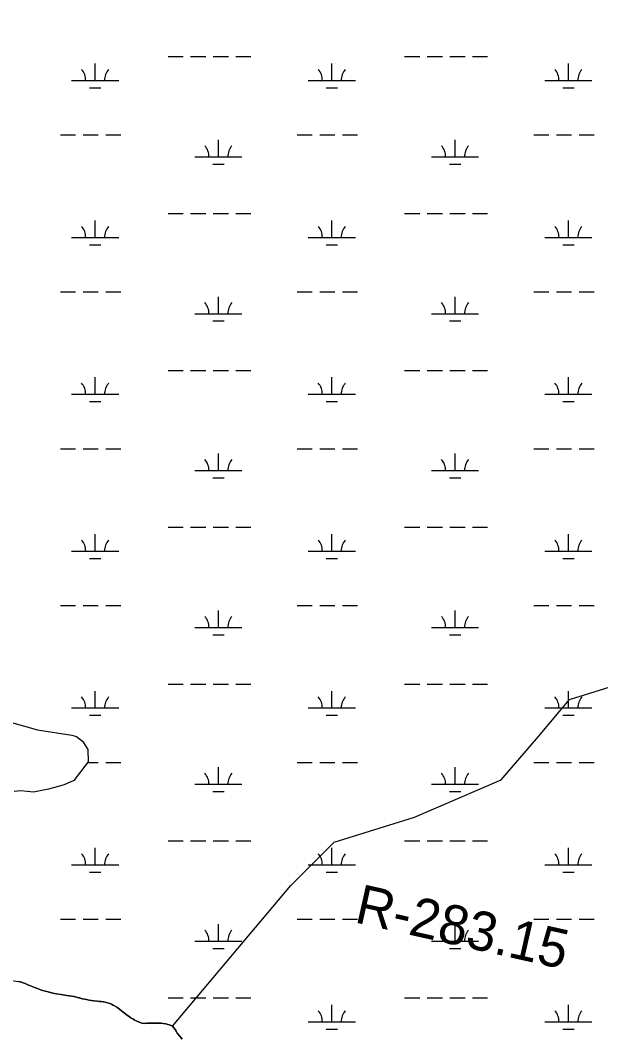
# Model space of a CAD drawing. Extents: x 3192927 to 3230760, y 831141 to 856475.
# Drawn here: x 3214470 to 3215700, y 838041 to 840200 of the extents above; entities that cross this region are included whole.
import ezdxf

# ---------------------------------------------------------------- set-up
doc = ezdxf.new("R2010")
doc.units = 0
for name, color, linetype in [('V-RIVR-RANG-IDEN', 7, 'Continuous'), ('V-SITE-VEGE', 7, 'Continuous'), ('V-TOPO-SHOR', 7, 'Continuous'), ('V-WETL-SWMP', 7, 'Continuous')]:
    doc.layers.add(name, color=color, linetype=linetype)

msp = doc.modelspace()

# ---------------------------------------------------------------- linework, layer by layer
at = {"layer": 'V-SITE-VEGE'}
for p, q in [((3214450.5, 838711.3), (3214505.8, 838695.7)), ((3214505.8, 838695.7), (3214578.9, 838684.3)), ((3214578.9, 838684.3), (3214588.3, 838681.6)), ((3214588.3, 838681.6), (3214601.1, 838671.3)), ((3214601.1, 838671.3), (3214612.8, 838654.1)), ((3214612.8, 838654.1), (3214613.1, 838627.8)), ((3214613.1, 838627.8), (3214583.3, 838588.2)), ((3214562.2, 838579.1), (3214529.4, 838569.5)), ((3214583.3, 838588.2), (3214562.2, 838579.1)), ((3214470.9, 838566.2), (3214456.3, 838564.5)), ((3214497.4, 838563.6), (3214470.9, 838566.2)), ((3214529.4, 838569.5), (3214497.4, 838563.6)), ((3214451.5, 838164.2), (3214469.8, 838160.9)), ((3214469.8, 838160.9), (3214475.6, 838159.1)), ((3214475.6, 838159.1), (3214479.8, 838157.5)), ((3214479.8, 838157.5), (3214484.2, 838155.6)), ((3214484.2, 838155.6), (3214491.2, 838153)), ((3214491.2, 838153), (3214501.8, 838148.5)), ((3214501.8, 838148.5), (3214506.2, 838146.7)), ((3214506.2, 838146.7), (3214512.3, 838144.4)), ((3214512.3, 838144.4), (3214517.3, 838142.6)), ((3214517.3, 838142.6), (3214522.5, 838141.1)), ((3214522.5, 838141.1), (3214525.5, 838140.5)), ((3214525.5, 838140.5), (3214538.3, 838137.4)), ((3214538.3, 838137.4), (3214541.9, 838136.6)), ((3214541.9, 838136.6), (3214546, 838136)), ((3214546, 838136), (3214556, 838134.1)), ((3214556, 838134.1), (3214564.2, 838132.9)), ((3214564.2, 838132.9), (3214583.5, 838129.7)), ((3214583.5, 838129.7), (3214590.7, 838128.1)), ((3214590.7, 838128.1), (3214601.1, 838125.4)), ((3214601.1, 838125.4), (3214609.8, 838123.6)), ((3214609.8, 838123.6), (3214615.8, 838122.3)), ((3214615.8, 838122.3), (3214625.2, 838120.9)), ((3214625.2, 838120.9), (3214633, 838120.4)), ((3214633, 838120.4), (3214637.7, 838119.8)), ((3214637.7, 838119.8), (3214641.1, 838119.6)), ((3214641.1, 838119.6), (3214649.7, 838118.3)), ((3214649.7, 838118.3), (3214659.3, 838115.1)), ((3214659.3, 838115.1), (3214662.9, 838113.6)), ((3214662.9, 838113.6), (3214666.1, 838112)), ((3214666.1, 838112), (3214669.3, 838110.2)), ((3214669.3, 838110.2), (3214673.9, 838107.5)), ((3214673.9, 838107.5), (3214677.3, 838105.3)), ((3214677.3, 838105.3), (3214680.1, 838102.9)), ((3214680.1, 838102.9), (3214684.1, 838099.8)), ((3214684.1, 838099.8), (3214687.3, 838096.8)), ((3214687.3, 838096.8), (3214696.5, 838089.7)), ((3214696.5, 838089.7), (3214700.1, 838087.5)), ((3214700.1, 838087.5), (3214704.7, 838084.3)), ((3214704.7, 838084.3), (3214707.9, 838082.6)), ((3214707.9, 838082.6), (3214711.1, 838080.6)), ((3214711.1, 838080.6), (3214718.3, 838076.8)), ((3214718.3, 838076.8), (3214725, 838074.5)), ((3214725, 838074.5), (3214728.2, 838073.7)), ((3214728.2, 838073.7), (3214732.4, 838073.1)), ((3214732.4, 838073.1), (3214737.6, 838073.2)), ((3214737.6, 838073.2), (3214741.6, 838073.4)), ((3214741.6, 838073.4), (3214747.3, 838073.4)), ((3214747.3, 838073.4), (3214751.9, 838073.7)), ((3214751.9, 838073.7), (3214763.9, 838073.7)), ((3214763.9, 838073.7), (3214768.1, 838073.3)), ((3214768.1, 838073.3), (3214772.4, 838072.8)), ((3214772.4, 838072.8), (3214778.2, 838072.2)), ((3214778.2, 838072.2), (3214782, 838071)), ((3214782, 838071), (3214785.8, 838070.1)), ((3214785.8, 838070.1), (3214792.4, 838066.9)), ((3214792.4, 838066.9), (3214795.4, 838063.3)), ((3214795.4, 838063.3), (3214797.6, 838060)), ((3214797.6, 838060), (3214799.8, 838056.2)), ((3214799.8, 838056.2), (3214802.4, 838052.6)), ((3214802.4, 838052.6), (3214807.4, 838046.3)), ((3214807.4, 838046.3), (3214809.9, 838042.9)), ((3214809.9, 838042.9), (3214812.9, 838039.5))]:
    msp.add_line(p, q, dxfattribs=at)
at = {"layer": 'V-TOPO-SHOR'}
for points in [[(3214792.4, 838066.9), (3215042.9, 838365.4), (3215134.9, 838457.5), (3215305.7, 838510.2), (3215489.6, 838589.2), (3215568.4, 838681.3), (3215634.1, 838760.2), (3215804.9, 838812.9), (3215883.7, 838891.9), (3216094, 838931.5), (3216225.3, 839023.6), (3216238.4, 839076.2), (3216251.5, 839168.2), (3216251.4, 839299.6), (3216251.2, 839483.6), (3216277.3, 839693.9), (3216303.5, 839878), (3216434.7, 840101.5), (3216526.6, 840272.5), (3216565.9, 840456.5), (3216552.6, 840627.4), (3216591.9, 840785.1), (3216631.2, 840903.4), (3216657.5, 840956)], [(3214450.5, 838711.3), (3214505.8, 838695.7), (3214578.9, 838684.3), (3214588.3, 838681.6), (3214601.1, 838671.3), (3214612.8, 838654.1), (3214613.1, 838627.8), (3214583.3, 838588.2), (3214562.2, 838579.1), (3214529.4, 838569.5), (3214497.4, 838563.6), (3214470.9, 838566.2), (3214456.3, 838564.5)], [(3214556, 838134.1), (3214550, 838135.2), (3214546, 838136), (3214541.9, 838136.6), (3214538.3, 838137.4), (3214533.7, 838138.5), (3214528.5, 838139.7), (3214525.5, 838140.5), (3214522.5, 838141.1), (3214517.3, 838142.6), (3214512.3, 838144.4), (3214506.2, 838146.7), (3214501.8, 838148.5), (3214491.2, 838153), (3214484.2, 838155.6), (3214479.8, 838157.5), (3214475.6, 838159.1), (3214469.8, 838160.9), (3214465.4, 838161.6)], [(3214812.9, 838039.5), (3214809.9, 838042.9), (3214807.4, 838046.3), (3214802.4, 838052.6), (3214799.8, 838056.2), (3214797.6, 838060), (3214795.4, 838063.3), (3214792.4, 838066.9), (3214785.8, 838070.1), (3214782, 838071), (3214778.2, 838072.2), (3214772.4, 838072.8), (3214768.1, 838073.3), (3214763.9, 838073.7), (3214758.9, 838073.7), (3214755.5, 838073.7), (3214751.9, 838073.7), (3214747.3, 838073.4), (3214741.6, 838073.4), (3214737.6, 838073.2), (3214732.4, 838073.1), (3214728.2, 838073.7), (3214725, 838074.5), (3214722, 838075.5), (3214718.3, 838076.8), (3214714.1, 838079), (3214711.1, 838080.6), (3214707.9, 838082.6), (3214704.7, 838084.3), (3214700.1, 838087.5), (3214696.5, 838089.7), (3214690.3, 838094.4), (3214687.3, 838096.8), (3214684.1, 838099.8), (3214680.1, 838102.9), (3214677.3, 838105.3), (3214673.9, 838107.5), (3214669.3, 838110.2), (3214666.1, 838112), (3214662.9, 838113.6), (3214659.3, 838115.1), (3214654.5, 838116.7), (3214649.7, 838118.3), (3214646.3, 838118.9), (3214641.1, 838119.6), (3214637.7, 838119.8), (3214633, 838120.4), (3214625.2, 838120.9), (3214615.8, 838122.3), (3214609.8, 838123.6), (3214601.1, 838125.4), (3214595.3, 838126.9), (3214590.7, 838128.1), (3214583.5, 838129.7), (3214577.9, 838130.6), (3214572.4, 838131.6), (3214564.2, 838132.9), (3214559.8, 838133.5), (3214556, 838134.1)]]:
    msp.add_lwpolyline(points, dxfattribs=at)
at = {"layer": 'V-WETL-SWMP'}
for p, q in [((3214782.7, 840123.4), (3214814.7, 840123.4)), ((3214830.7, 840123.4), (3214862.7, 840123.4)), ((3214878.7, 840123.4), (3214910.7, 840123.4)), ((3214926.7, 840123.4), (3214958.7, 840123.4)), ((3215284.6, 840123.4), (3215316.6, 840123.4)), ((3215332.6, 840123.4), (3215364.6, 840123.4)), ((3215380.6, 840123.4), (3215412.6, 840123.4)), ((3215428.6, 840123.4), (3215460.6, 840123.4)), ((3214628.1, 840072.6), (3214628.1, 840108.6)), ((3215130, 840072.6), (3215130, 840108.6)), ((3215631.9, 840072.6), (3215631.9, 840108.6)), ((3214578.1, 840072.6), (3214678.1, 840072.6)), ((3215080, 840072.6), (3215180, 840072.6)), ((3215581.9, 840072.6), (3215681.9, 840072.6)), ((3214616.1, 840057.2), (3214640.1, 840057.2)), ((3215118, 840057.2), (3215142, 840057.2)), ((3215619.9, 840057.2), (3215643.9, 840057.2)), ((3214554.7, 839957.2), (3214586.7, 839957.2)), ((3214602.7, 839957.2), (3214634.7, 839957.2)), ((3214650.7, 839957.2), (3214682.7, 839957.2)), ((3214889.6, 839910.8), (3214889.6, 839946.8)), ((3215056.6, 839957.2), (3215088.6, 839957.2)), ((3215104.6, 839957.2), (3215136.6, 839957.2)), ((3215152.6, 839957.2), (3215184.6, 839957.2)), ((3215391.5, 839910.8), (3215391.5, 839946.8)), ((3215558.5, 839957.2), (3215590.5, 839957.2)), ((3215606.5, 839957.2), (3215638.5, 839957.2)), ((3215654.5, 839957.2), (3215686.5, 839957.2)), ((3214839.6, 839910.8), (3214939.6, 839910.8)), ((3214877.6, 839895.3), (3214901.6, 839895.3)), ((3215341.5, 839910.8), (3215441.5, 839910.8)), ((3215379.5, 839895.3), (3215403.5, 839895.3)), ((3214782.7, 839790.7), (3214814.7, 839790.7)), ((3214830.7, 839790.7), (3214862.7, 839790.7)), ((3214878.7, 839790.7), (3214910.7, 839790.7)), ((3214926.7, 839790.7), (3214958.7, 839790.7)), ((3215284.6, 839790.7), (3215316.6, 839790.7)), ((3215332.6, 839790.7), (3215364.6, 839790.7)), ((3215380.6, 839790.7), (3215412.6, 839790.7)), ((3215428.6, 839790.7), (3215460.6, 839790.7)), ((3214628.1, 839740), (3214628.1, 839776)), ((3215130, 839740), (3215130, 839776)), ((3215631.9, 839740), (3215631.9, 839776)), ((3214578.1, 839740), (3214678.1, 839740)), ((3214616.1, 839724.5), (3214640.1, 839724.5)), ((3215080, 839740), (3215180, 839740)), ((3215118, 839724.5), (3215142, 839724.5)), ((3215581.9, 839740), (3215681.9, 839740)), ((3215619.9, 839724.5), (3215643.9, 839724.5)), ((3214554.7, 839624.5), (3214586.7, 839624.5)), ((3214602.7, 839624.5), (3214634.7, 839624.5)), ((3214650.7, 839624.5), (3214682.7, 839624.5)), ((3215056.6, 839624.5), (3215088.6, 839624.5)), ((3215104.6, 839624.5), (3215136.6, 839624.5)), ((3215152.6, 839624.5), (3215184.6, 839624.5)), ((3215558.5, 839624.5), (3215590.5, 839624.5)), ((3215606.5, 839624.5), (3215638.5, 839624.5)), ((3215654.5, 839624.5), (3215686.5, 839624.5)), ((3214889.6, 839578.1), (3214889.6, 839614.1)), ((3215391.5, 839578.1), (3215391.5, 839614.1)), ((3214839.6, 839578.1), (3214939.6, 839578.1)), ((3215341.5, 839578.1), (3215441.5, 839578.1)), ((3214877.6, 839562.7), (3214901.6, 839562.7)), ((3215379.5, 839562.7), (3215403.5, 839562.7)), ((3214628.1, 839407.3), (3214628.1, 839443.3)), ((3214782.7, 839458), (3214814.7, 839458)), ((3214830.7, 839458), (3214862.7, 839458)), ((3214878.7, 839458), (3214910.7, 839458)), ((3214926.7, 839458), (3214958.7, 839458)), ((3215130, 839407.3), (3215130, 839443.3)), ((3215284.6, 839458), (3215316.6, 839458)), ((3215332.6, 839458), (3215364.6, 839458)), ((3215380.6, 839458), (3215412.6, 839458)), ((3215428.6, 839458), (3215460.6, 839458)), ((3215631.9, 839407.3), (3215631.9, 839443.3)), ((3214578.1, 839407.3), (3214678.1, 839407.3)), ((3215080, 839407.3), (3215180, 839407.3)), ((3215581.9, 839407.3), (3215681.9, 839407.3)), ((3214616.1, 839391.8), (3214640.1, 839391.8)), ((3215118, 839391.8), (3215142, 839391.8)), ((3215619.9, 839391.8), (3215643.9, 839391.8)), ((3214554.7, 839291.8), (3214586.7, 839291.8)), ((3214602.7, 839291.8), (3214634.7, 839291.8)), ((3214650.7, 839291.8), (3214682.7, 839291.8)), ((3215056.6, 839291.8), (3215088.6, 839291.8)), ((3215104.6, 839291.8), (3215136.6, 839291.8)), ((3215152.6, 839291.8), (3215184.6, 839291.8)), ((3215558.5, 839291.8), (3215590.5, 839291.8)), ((3215606.5, 839291.8), (3215638.5, 839291.8)), ((3215654.5, 839291.8), (3215686.5, 839291.8)), ((3214889.6, 839245.4), (3214889.6, 839281.4)), ((3215391.5, 839245.4), (3215391.5, 839281.4)), ((3214839.6, 839245.4), (3214939.6, 839245.4)), ((3214877.6, 839230), (3214901.6, 839230)), ((3215341.5, 839245.4), (3215441.5, 839245.4)), ((3215379.5, 839230), (3215403.5, 839230)), ((3214782.7, 839125.3), (3214814.7, 839125.3)), ((3214830.7, 839125.3), (3214862.7, 839125.3)), ((3214878.7, 839125.3), (3214910.7, 839125.3)), ((3214926.7, 839125.3), (3214958.7, 839125.3)), ((3215284.6, 839125.3), (3215316.6, 839125.3)), ((3215332.6, 839125.3), (3215364.6, 839125.3)), ((3215380.6, 839125.3), (3215412.6, 839125.3)), ((3215428.6, 839125.3), (3215460.6, 839125.3)), ((3214628.1, 839074.6), (3214628.1, 839110.6)), ((3215130, 839074.6), (3215130, 839110.6)), ((3215631.9, 839074.6), (3215631.9, 839110.6)), ((3214578.1, 839074.6), (3214678.1, 839074.6)), ((3214616.1, 839059.2), (3214640.1, 839059.2)), ((3215080, 839074.6), (3215180, 839074.6)), ((3215118, 839059.2), (3215142, 839059.2)), ((3215581.9, 839074.6), (3215681.9, 839074.6)), ((3215619.9, 839059.2), (3215643.9, 839059.2)), ((3214554.7, 838959.2), (3214586.7, 838959.2)), ((3214602.7, 838959.2), (3214634.7, 838959.2)), ((3214650.7, 838959.2), (3214682.7, 838959.2)), ((3214889.6, 838912.7), (3214889.6, 838948.7)), ((3215056.6, 838959.2), (3215088.6, 838959.2)), ((3215104.6, 838959.2), (3215136.6, 838959.2)), ((3215152.6, 838959.2), (3215184.6, 838959.2)), ((3215391.5, 838912.7), (3215391.5, 838948.7)), ((3215558.5, 838959.2), (3215590.5, 838959.2)), ((3215606.5, 838959.2), (3215638.5, 838959.2)), ((3215654.5, 838959.2), (3215686.5, 838959.2)), ((3214839.6, 838912.7), (3214939.6, 838912.7)), ((3215341.5, 838912.7), (3215441.5, 838912.7)), ((3214877.6, 838897.3), (3214901.6, 838897.3)), ((3215379.5, 838897.3), (3215403.5, 838897.3)), ((3214628.1, 838741.9), (3214628.1, 838777.9)), ((3214782.7, 838792.7), (3214814.7, 838792.7)), ((3214830.7, 838792.7), (3214862.7, 838792.7)), ((3214878.7, 838792.7), (3214910.7, 838792.7)), ((3214926.7, 838792.7), (3214958.7, 838792.7)), ((3215130, 838741.9), (3215130, 838777.9)), ((3215284.6, 838792.7), (3215316.6, 838792.7)), ((3215332.6, 838792.7), (3215364.6, 838792.7)), ((3215380.6, 838792.7), (3215412.6, 838792.7)), ((3215428.6, 838792.7), (3215460.6, 838792.7)), ((3215631.9, 838741.9), (3215631.9, 838777.9)), ((3214578.1, 838741.9), (3214678.1, 838741.9)), ((3215080, 838741.9), (3215180, 838741.9)), ((3215581.9, 838741.9), (3215681.9, 838741.9)), ((3214450.5, 838711.3), (3214505.8, 838695.7)), ((3214616.1, 838726.5), (3214640.1, 838726.5)), ((3215118, 838726.5), (3215142, 838726.5)), ((3215619.9, 838726.5), (3215643.9, 838726.5)), ((3214505.8, 838695.7), (3214578.9, 838684.3)), ((3214578.9, 838684.3), (3214588.3, 838681.6)), ((3214588.3, 838681.6), (3214601.1, 838671.3)), ((3214601.1, 838671.3), (3214612.8, 838654.1)), ((3214612.8, 838654.1), (3214613.1, 838627.8)), ((3214613.1, 838627.8), (3214583.3, 838588.2)), ((3214612.2, 838626.5), (3214634.7, 838626.5)), ((3214650.7, 838626.5), (3214682.7, 838626.5)), ((3215056.6, 838626.5), (3215088.6, 838626.5)), ((3215104.6, 838626.5), (3215136.6, 838626.5)), ((3215152.6, 838626.5), (3215184.6, 838626.5)), ((3215558.5, 838626.5), (3215590.5, 838626.5)), ((3215606.5, 838626.5), (3215638.5, 838626.5)), ((3215654.5, 838626.5), (3215686.5, 838626.5)), ((3214889.6, 838580.1), (3214889.6, 838616.1)), ((3215391.5, 838580.1), (3215391.5, 838616.1)), ((3214562.2, 838579.1), (3214529.4, 838569.5)), ((3214583.3, 838588.2), (3214562.2, 838579.1)), ((3214839.6, 838580.1), (3214939.6, 838580.1)), ((3215341.5, 838580.1), (3215441.5, 838580.1)), ((3214470.9, 838566.2), (3214456.3, 838564.5)), ((3214497.4, 838563.6), (3214470.9, 838566.2)), ((3214529.4, 838569.5), (3214497.4, 838563.6)), ((3214877.6, 838564.6), (3214901.6, 838564.6)), ((3215379.5, 838564.6), (3215403.5, 838564.6)), ((3214782.7, 838460), (3214814.7, 838460)), ((3214830.7, 838460), (3214862.7, 838460)), ((3214878.7, 838460), (3214910.7, 838460)), ((3214926.7, 838460), (3214958.7, 838460)), ((3215284.6, 838460), (3215316.6, 838460)), ((3215332.6, 838460), (3215364.6, 838460)), ((3215380.6, 838460), (3215412.6, 838460)), ((3215428.6, 838460), (3215460.6, 838460)), ((3214628.1, 838409.3), (3214628.1, 838445.3)), ((3215130, 838409.3), (3215130, 838445.3)), ((3215631.9, 838409.3), (3215631.9, 838445.3)), ((3214578.1, 838409.3), (3214678.1, 838409.3)), ((3215080, 838409.3), (3215180, 838409.3)), ((3215581.9, 838409.3), (3215681.9, 838409.3)), ((3214616.1, 838393.8), (3214640.1, 838393.8)), ((3215118, 838393.8), (3215142, 838393.8)), ((3215619.9, 838393.8), (3215643.9, 838393.8)), ((3214554.7, 838293.8), (3214586.7, 838293.8)), ((3214602.7, 838293.8), (3214634.7, 838293.8)), ((3214650.7, 838293.8), (3214682.7, 838293.8)), ((3214889.6, 838247.4), (3214889.6, 838283.4)), ((3215056.6, 838293.8), (3215088.6, 838293.8)), ((3215104.6, 838293.8), (3215136.6, 838293.8)), ((3215152.6, 838293.8), (3215184.6, 838293.8)), ((3215391.5, 838247.4), (3215391.5, 838283.4)), ((3215558.5, 838293.8), (3215590.5, 838293.8)), ((3215606.5, 838293.8), (3215638.5, 838293.8)), ((3215654.5, 838293.8), (3215686.5, 838293.8)), ((3214839.6, 838247.4), (3214939.6, 838247.4)), ((3215341.5, 838247.4), (3215441.5, 838247.4)), ((3214877.6, 838232), (3214901.6, 838232)), ((3215379.5, 838232), (3215403.5, 838232)), ((3214465.4, 838161.6), (3214469.8, 838160.9)), ((3214469.8, 838160.9), (3214475.6, 838159.1)), ((3214475.6, 838159.1), (3214479.8, 838157.5)), ((3214479.8, 838157.5), (3214484.2, 838155.6)), ((3214484.2, 838155.6), (3214491.2, 838153)), ((3214491.2, 838153), (3214501.8, 838148.5)), ((3214501.8, 838148.5), (3214506.2, 838146.7)), ((3214506.2, 838146.7), (3214512.3, 838144.4)), ((3214512.3, 838144.4), (3214517.3, 838142.6)), ((3214517.3, 838142.6), (3214522.5, 838141.1)), ((3214522.5, 838141.1), (3214525.5, 838140.5)), ((3214525.5, 838140.5), (3214528.5, 838139.7)), ((3214528.5, 838139.7), (3214533.7, 838138.5)), ((3214533.7, 838138.5), (3214538.3, 838137.4)), ((3214538.3, 838137.4), (3214541.9, 838136.6)), ((3214541.9, 838136.6), (3214546, 838136)), ((3214546, 838136), (3214556, 838134.1)), ((3214556, 838134.1), (3214559.8, 838133.5)), ((3214559.8, 838133.5), (3214564.2, 838132.9)), ((3214564.2, 838132.9), (3214572.4, 838131.6)), ((3214572.4, 838131.6), (3214583.5, 838129.7)), ((3214583.5, 838129.7), (3214590.7, 838128.1)), ((3214590.7, 838128.1), (3214595.3, 838126.9)), ((3214595.3, 838126.9), (3214601.1, 838125.4)), ((3214601.1, 838125.4), (3214609.8, 838123.6)), ((3214782.7, 838127.3), (3214814.7, 838127.3)), ((3214830.7, 838127.3), (3214862.7, 838127.3)), ((3214878.7, 838127.3), (3214910.7, 838127.3)), ((3214926.7, 838127.3), (3214958.7, 838127.3)), ((3215284.6, 838127.3), (3215316.6, 838127.3)), ((3215332.6, 838127.3), (3215364.6, 838127.3)), ((3215380.6, 838127.3), (3215412.6, 838127.3)), ((3215428.6, 838127.3), (3215460.6, 838127.3)), ((3214609.8, 838123.6), (3214615.8, 838122.3)), ((3214615.8, 838122.3), (3214625.2, 838120.9)), ((3214625.2, 838120.9), (3214633, 838120.4)), ((3214633, 838120.4), (3214637.7, 838119.8)), ((3214637.7, 838119.8), (3214641.1, 838119.6)), ((3214641.1, 838119.6), (3214646.3, 838118.9)), ((3214646.3, 838118.9), (3214649.7, 838118.3)), ((3214649.7, 838118.3), (3214659.3, 838115.1)), ((3214659.3, 838115.1), (3214662.9, 838113.6)), ((3214662.9, 838113.6), (3214666.1, 838112)), ((3214666.1, 838112), (3214669.3, 838110.2)), ((3214669.3, 838110.2), (3214673.9, 838107.5)), ((3214673.9, 838107.5), (3214677.3, 838105.3)), ((3214677.3, 838105.3), (3214680.1, 838102.9)), ((3214680.1, 838102.9), (3214684.1, 838099.8)), ((3215130, 838076.6), (3215130, 838112.6)), ((3215631.9, 838076.6), (3215631.9, 838112.6)), ((3214684.1, 838099.8), (3214687.3, 838096.8)), ((3214687.3, 838096.8), (3214690.3, 838094.4)), ((3214690.3, 838094.4), (3214696.5, 838089.7)), ((3214696.5, 838089.7), (3214700.1, 838087.5)), ((3214700.1, 838087.5), (3214704.7, 838084.3)), ((3214704.7, 838084.3), (3214707.9, 838082.6)), ((3214707.9, 838082.6), (3214711.1, 838080.6)), ((3214711.1, 838080.6), (3214714.1, 838079)), ((3214714.1, 838079), (3214718.3, 838076.8)), ((3214718.3, 838076.8), (3214722, 838075.5)), ((3214722, 838075.5), (3214725, 838074.5)), ((3214725, 838074.5), (3214728.2, 838073.7)), ((3214728.2, 838073.7), (3214732.4, 838073.1)), ((3214732.4, 838073.1), (3214737.6, 838073.2)), ((3214737.6, 838073.2), (3214741.6, 838073.4)), ((3214741.6, 838073.4), (3214747.3, 838073.4)), ((3214747.3, 838073.4), (3214751.9, 838073.7)), ((3214751.9, 838073.7), (3214763.9, 838073.7)), ((3214763.9, 838073.7), (3214768.1, 838073.3)), ((3214768.1, 838073.3), (3214772.4, 838072.8)), ((3214772.4, 838072.8), (3214778.2, 838072.2)), ((3214778.2, 838072.2), (3214782, 838071)), ((3214782, 838071), (3214785.8, 838070.1)), ((3214785.8, 838070.1), (3214792.4, 838066.9)), ((3214792.4, 838066.9), (3214795.4, 838063.3)), ((3214795.4, 838063.3), (3214797.6, 838060)), ((3214797.6, 838060), (3214799.8, 838056.2)), ((3215080, 838076.6), (3215180, 838076.6)), ((3215118, 838061.1), (3215142, 838061.1)), ((3215581.9, 838076.6), (3215681.9, 838076.6)), ((3215619.9, 838061.1), (3215643.9, 838061.1)), ((3214799.8, 838056.2), (3214802.4, 838052.6)), ((3214802.4, 838052.6), (3214807.4, 838046.3)), ((3214807.4, 838046.3), (3214809.9, 838042.9)), ((3214809.9, 838042.9), (3214812.9, 838039.5))]:
    msp.add_line(p, q, dxfattribs=at)
for centre, start, end in [((3214572.9, 840073.1), 359.2282, 40.7718), ((3214683.4, 840073.1), 139.2282, 180.7718), ((3215074.8, 840073.1), 359.2282, 40.7718), ((3215185.3, 840073.1), 139.2282, 180.7718), ((3215576.7, 840073.1), 359.2282, 40.7718), ((3215687.2, 840073.1), 139.2282, 180.7718), ((3214834.3, 839911.2), 359.2282, 40.7718), ((3214944.8, 839911.2), 139.2282, 180.7718), ((3215336.2, 839911.2), 359.2282, 40.7718), ((3215446.7, 839911.2), 139.2282, 180.7718), ((3214572.9, 839740.4), 359.2282, 40.7718), ((3214683.4, 839740.4), 139.2282, 180.7718), ((3215074.8, 839740.4), 359.2282, 40.7718), ((3215185.3, 839740.4), 139.2282, 180.7718), ((3215576.7, 839740.4), 359.2282, 40.7718), ((3215687.2, 839740.4), 139.2282, 180.7718), ((3214834.3, 839578.6), 359.2282, 40.7718), ((3214944.8, 839578.6), 139.2282, 180.7718), ((3215336.2, 839578.6), 359.2282, 40.7718), ((3215446.7, 839578.6), 139.2282, 180.7718), ((3214572.9, 839407.7), 359.2282, 40.7718), ((3214683.4, 839407.7), 139.2282, 180.7718), ((3215074.8, 839407.7), 359.2282, 40.7718), ((3215185.3, 839407.7), 139.2282, 180.7718), ((3215576.7, 839407.7), 359.2282, 40.7718), ((3215687.2, 839407.7), 139.2282, 180.7718), ((3214834.3, 839245.9), 359.2282, 40.7718), ((3214944.8, 839245.9), 139.2282, 180.7718), ((3215336.2, 839245.9), 359.2282, 40.7718), ((3215446.7, 839245.9), 139.2282, 180.7718), ((3214572.9, 839075.1), 359.2282, 40.7718), ((3214683.4, 839075.1), 139.2282, 180.7718), ((3215074.8, 839075.1), 359.2282, 40.7718), ((3215185.3, 839075.1), 139.2282, 180.7718), ((3215576.7, 839075.1), 359.2282, 40.7718), ((3215687.2, 839075.1), 139.2282, 180.7718), ((3214834.3, 838913.2), 359.2282, 40.7718), ((3214944.8, 838913.2), 139.2282, 180.7718), ((3215336.2, 838913.2), 359.2282, 40.7718), ((3215446.7, 838913.2), 139.2282, 180.7718), ((3214572.9, 838742.4), 359.2282, 40.7718), ((3214683.4, 838742.4), 139.2282, 180.7718), ((3215074.8, 838742.4), 359.2282, 40.7718), ((3215185.3, 838742.4), 139.2282, 180.7718), ((3215576.7, 838742.4), 359.2282, 40.7718), ((3215687.2, 838742.4), 139.2282, 180.7718), ((3214834.3, 838580.5), 359.2282, 40.7718), ((3214944.8, 838580.5), 139.2282, 180.7718), ((3215336.2, 838580.5), 359.2282, 40.7718), ((3215446.7, 838580.5), 139.2282, 180.7718), ((3214572.9, 838409.7), 359.2282, 40.7718), ((3214683.4, 838409.7), 139.2282, 180.7718), ((3215074.8, 838409.7), 359.2282, 40.7718), ((3215185.3, 838409.7), 139.2282, 180.7718), ((3215576.7, 838409.7), 359.2282, 40.7718), ((3215687.2, 838409.7), 139.2282, 180.7718), ((3214834.3, 838247.9), 359.2282, 40.7718), ((3214944.8, 838247.9), 139.2282, 180.7718), ((3215336.2, 838247.9), 359.2282, 40.7718), ((3215446.7, 838247.9), 139.2282, 180.7718), ((3215074.8, 838077), 359.2282, 40.7718), ((3215185.3, 838077), 139.2282, 180.7718), ((3215576.7, 838077), 359.2282, 40.7718), ((3215687.2, 838077), 139.2282, 180.7718)]:
    msp.add_arc(centre, 35.2, start, end, dxfattribs=at)

# ---------------------------------------------------------------- texts
at = {"layer": 'V-RIVR-RANG-IDEN'}
msp.add_text('R-283.15', height=83, rotation=347.3196, dxfattribs=at).set_placement((3215175.7, 838287.8))

doc.saveas('drawing.dxf')
